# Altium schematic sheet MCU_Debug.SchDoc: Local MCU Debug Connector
size A4; DocumentNumber: 7; SheetNumber: 7; SheetTotal: 12
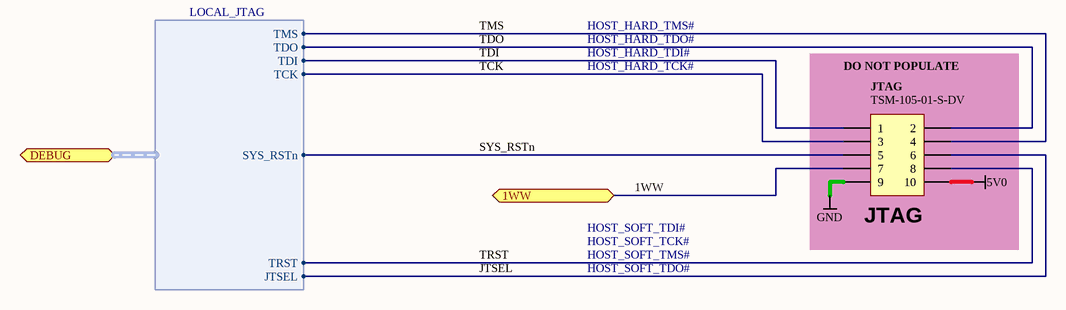
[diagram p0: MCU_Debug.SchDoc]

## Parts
JTAG  TSM-105-01-S-DV  [TSM-105-01-DV]  (no BOM)

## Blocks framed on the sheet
JTAG: JTAG

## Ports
1WW (bidir), DEBUG (harness LOCAL_JTAG)

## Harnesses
LOCAL_JTAG: TMS, TDO, TDI, TCK, SYS_RSTn, TRST, JTSEL

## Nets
5V0: JTAG.10
GND: JTAG.9
1WW: JTAG.7 ; port 1WW
JTSEL: JTAG.6 ; port DEBUG.JTSEL
SYS_RSTn: JTAG.5 ; port DEBUG.SYS_RSTn
TCK: JTAG.3 ; port DEBUG.TCK
TDI: JTAG.1 ; port DEBUG.TDI
TDO: JTAG.2 ; port DEBUG.TDO
TMS: JTAG.4 ; port DEBUG.TMS
TRST: JTAG.8 ; port DEBUG.TRST

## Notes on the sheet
- HOST_HARD_TMS#
- HOST_HARD_TDO#
- HOST_HARD_TDI#
- HOST_HARD_TCK#
- DO NOT POPULATE
- HOST_SOFT_TDI#
- HOST_SOFT_TCK#
- HOST_SOFT_TMS#
- HOST_SOFT_TDO#

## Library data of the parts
JTAG = D-300-0076: Non-Boxed Header IDC, 2 X 5 Pin SMD; Connector type: Boxed; Max Current: mA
